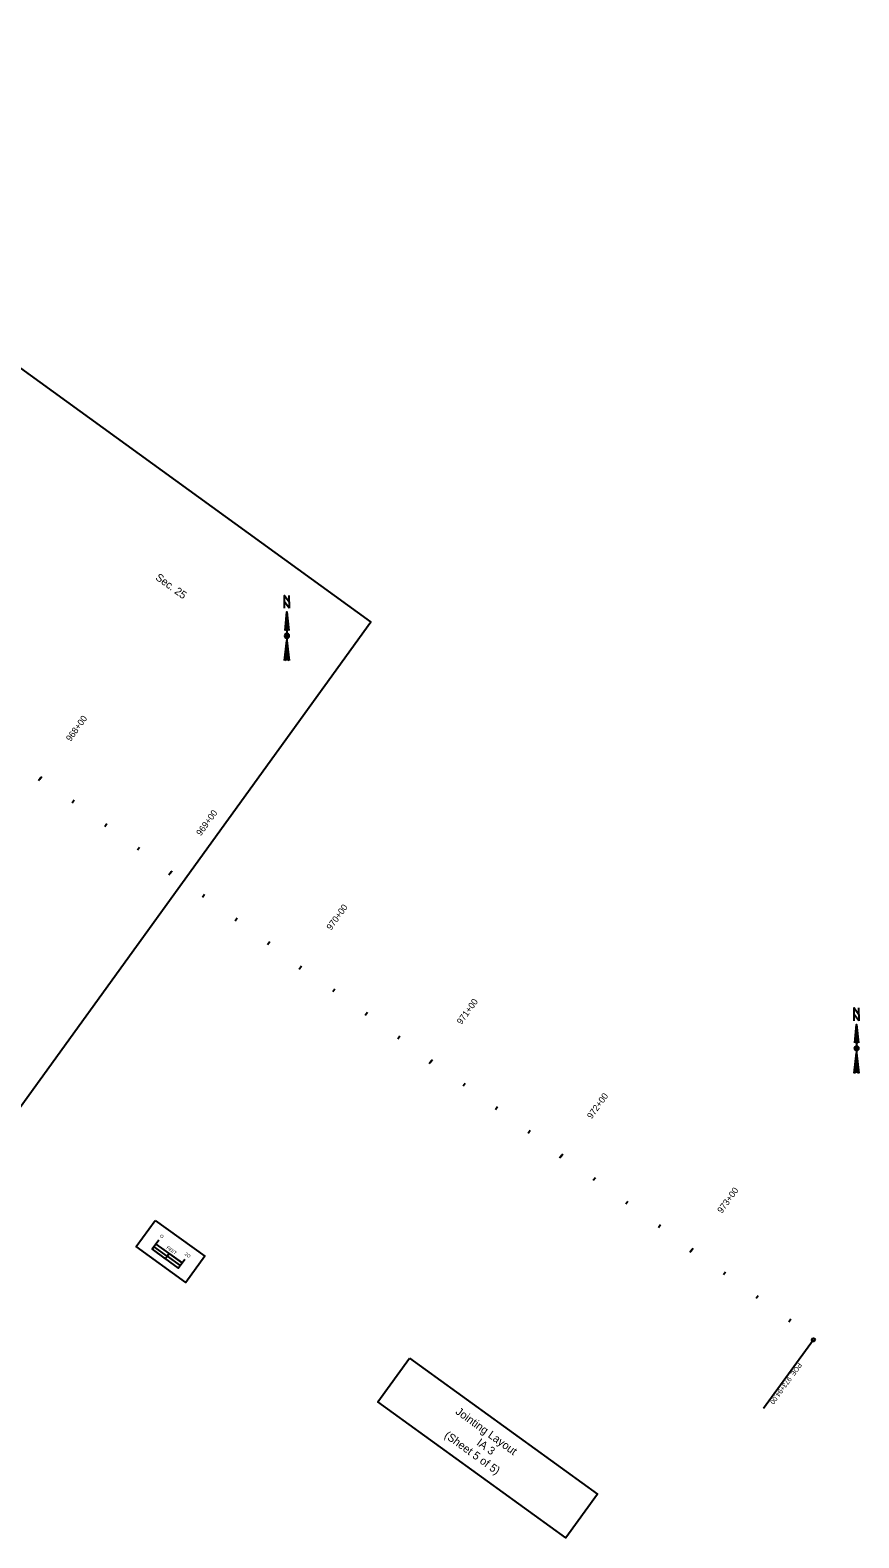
# Model space of a CAD drawing. Extents: x 14311466 to 14314811, y 8682098 to 8684603.
# Drawn here: x 14314296 to 14314811, y 8682098 to 8683035 of the extents above; entities that cross this region are included whole.
import ezdxf

# ---------------------------------------------------------------- set-up
doc = ezdxf.new("R2010")
doc.units = 0
for name, color, linetype in [('Cell', 7, 'Continuous'), ('Draft_8', 7, 'Continuous'), ('Draft_9', 7, 'Continuous'), ('NamedBoundary', 7, 'Continuous'), ('SheetText', 7, 'Continuous'), ('Text', 7, 'Continuous'), ('TextAlignment', 7, 'Continuous'), ('TextAlignmentLrg', 7, 'Continuous'), ('TextAlignmentSml', 7, 'Continuous')]:
    doc.layers.add(name, color=color, linetype=linetype)

msp = doc.modelspace()

# ---------------------------------------------------------------- linework, layer by layer
at = {"layer": 'Cell'}
for p, q in [((14314809.92, 8682417.14), (14314811.06, 8682405.73)), ((14314809.92, 8682417.14), (14314809.92, 8682387.48)), ((14314808.78, 8682405.73), (14314808.78, 8682405.73)), ((14314808.82, 8682405.84), (14314809.04, 8682406.07)), ((14314808.5, 8682386.9), (14314809.92, 8682399.45)), ((14314809.92, 8682400.88), (14314809.92, 8682400.88))]:
    msp.add_line(p, q, dxfattribs=at)
msp.add_lwpolyline([(14314811.35, 8682419.42), (14314808.5, 8682423.41), (14314808.5, 8682427.41), (14314811.35, 8682423.41)], close=True, dxfattribs=at)
for points in [[(14314808.5, 8682419.42), (14314808.5, 8682427.41), (14314811.35, 8682423.41), (14314811.35, 8682427.41)], [(14314808.78, 8682405.73), (14314809.92, 8682417.14), (14314809.92, 8682406.3)], [(14314809.92, 8682400.88), (14314809.92, 8682402.31), (14314808.5, 8682402.31)], [(14314811.35, 8682402.31), (14314809.92, 8682402.31), (14314809.92, 8682403.73)], [(14314809.92, 8682387.48), (14314809.92, 8682399.45), (14314811.35, 8682386.9)]]:
    msp.add_lwpolyline(points, dxfattribs=at)
for centre, radius, start, end in [((14314809.92, 8682404.87), 1.43, 90.02039, 143.12574), ((14314809.92, 8682404.88), 1.43, 36.84806, 90.02184), ((14314809.92, 8682402.31), 1.43, 90, 180), ((14314809.92, 8682402.31), 1.43, 180, 270), ((14314809.92, 8682402.31), 1.43, 0, 90), ((14314809.92, 8682402.31), 1.43, 270, 360), ((14314809.92, 8682385.41), 2.07, 89.98939, 133.61895), ((14314809.92, 8682385.41), 2.07, 46.40206, 90.00064)]:
    msp.add_arc(centre, radius, start, end, dxfattribs=at)
at = {"layer": 'Draft_8'}
for p, q in [((14314455.68, 8682673.47), (14314456.82, 8682662.06)), ((14314455.68, 8682673.47), (14314455.68, 8682643.81)), ((14314454.54, 8682662.06), (14314454.54, 8682662.06)), ((14314454.58, 8682662.17), (14314454.8, 8682662.4)), ((14314455.68, 8682657.21), (14314455.68, 8682657.21)), ((14314454.25, 8682643.24), (14314455.68, 8682655.79))]:
    msp.add_line(p, q, dxfattribs=at)
msp.add_lwpolyline([(14314457.11, 8682675.75), (14314454.25, 8682679.75), (14314454.25, 8682683.74), (14314457.11, 8682679.75)], close=True, dxfattribs=at)
for points in [[(14314454.25, 8682675.75), (14314454.25, 8682683.74), (14314457.11, 8682679.75), (14314457.11, 8682683.74)], [(14314454.54, 8682662.06), (14314455.68, 8682673.47), (14314455.68, 8682662.63)], [(14314455.68, 8682657.21), (14314455.68, 8682658.64), (14314454.25, 8682658.64)], [(14314457.11, 8682658.64), (14314455.68, 8682658.64), (14314455.68, 8682660.07)], [(14314455.68, 8682643.81), (14314455.68, 8682655.79), (14314457.11, 8682643.24)]]:
    msp.add_lwpolyline(points, dxfattribs=at)
for centre, radius, start, end in [((14314455.68, 8682658.64), 1.43, 90, 180), ((14314455.68, 8682658.64), 1.43, 180, 270), ((14314455.68, 8682661.21), 1.43, 90.02039, 143.12574), ((14314455.68, 8682661.21), 1.43, 36.84806, 90.02184), ((14314455.68, 8682658.64), 1.43, 0, 90), ((14314455.68, 8682658.64), 1.43, 270, 360), ((14314455.68, 8682641.74), 2.07, 89.98939, 133.61895), ((14314455.68, 8682641.74), 2.07, 46.40206, 90.00064)]:
    msp.add_arc(centre, radius, start, end, dxfattribs=at)
at = {"layer": 'Draft_9'}
msp.add_lwpolyline([(14314531.98, 8682209.86), (14314648.82, 8682125.27), (14314629.15, 8682098.1), (14314512.31, 8682182.7)], close=True, dxfattribs=at)
at = {"layer": 'NamedBoundary'}
msp.add_lwpolyline([(14314000.1, 8683035.05), (14313765.51, 8682711.06), (14314273.37, 8682343.35), (14314507.95, 8682667.35)], close=True, dxfattribs=at)
at = {"layer": 'SheetText'}
msp.add_line((14314380.03, 8682271.56), (14314382.38, 8682274.8), dxfattribs=at)
msp.add_line((14314380.03, 8682271.56), (14314382.38, 8682274.8), dxfattribs=at)
for points in [[(14314373.79, 8682295.34), (14314404.57, 8682273.05), (14314392.84, 8682256.85), (14314362.06, 8682279.14)], [(14314373.79, 8682295.34), (14314404.57, 8682273.05), (14314392.84, 8682256.85), (14314362.06, 8682279.14)], [(14314371.93, 8682277.42), (14314380.03, 8682271.56), (14314381.22, 8682273.19), (14314373.12, 8682279.05)], [(14314381.22, 8682273.19), (14314389.31, 8682267.32), (14314390.48, 8682268.93), (14314382.38, 8682274.8)]]:
    msp.add_lwpolyline(points, close=True, dxfattribs=at)
for points in [[(14314376.04, 8682283.09), (14314371.93, 8682277.42), (14314388.13, 8682265.69), (14314392.24, 8682271.36)], [(14314374.28, 8682280.66), (14314390.48, 8682268.93)]]:
    msp.add_lwpolyline(points, dxfattribs=at)
at = {"layer": 'TextAlignment'}
for p in [(14314783.09, 8682221.21), (14314752.13, 8682178.45)]:
    msp.add_line(p, (14314752.13, 8682178.45), dxfattribs=at)
msp.add_circle((14314783.09, 8682221.21), 1.07, dxfattribs=at)
at = {"layer": 'TextAlignmentLrg'}
for p, q in [((14314301.97, 8682569.57), (14314303.25, 8682571.34)), ((14314382.97, 8682510.92), (14314384.25, 8682512.69)), ((14314464.68, 8682453.27), (14314463.25, 8682451.28)), ((14314544.96, 8682393.63), (14314546.24, 8682395.4)), ((14314625.96, 8682334.98), (14314627.24, 8682336.75)), ((14314706.96, 8682276.34), (14314708.24, 8682278.11))]:
    msp.add_line(p, q, dxfattribs=at)
at = {"layer": 'TextAlignmentSml'}
for p, q in [((14314302.69, 8682570.56), (14314301.25, 8682568.58)), ((14314322.22, 8682554.91), (14314323.5, 8682556.67)), ((14314342.47, 8682540.24), (14314343.75, 8682542.01)), ((14314362.72, 8682525.58), (14314364, 8682527.35)), ((14314383.69, 8682511.91), (14314382.25, 8682509.93)), ((14314403.22, 8682496.26), (14314404.5, 8682498.03)), ((14314423.47, 8682481.6), (14314424.75, 8682483.37)), ((14314443.72, 8682466.94), (14314445, 8682468.71)), ((14314464.68, 8682453.27), (14314463.25, 8682451.28)), ((14314484.22, 8682437.61), (14314485.5, 8682439.38)), ((14314504.46, 8682422.95), (14314505.75, 8682424.72)), ((14314524.71, 8682408.29), (14314526, 8682410.06)), ((14314545.68, 8682394.62), (14314544.25, 8682392.64)), ((14314565.21, 8682378.97), (14314566.49, 8682380.74)), ((14314585.46, 8682364.31), (14314586.74, 8682366.08)), ((14314605.71, 8682349.65), (14314606.99, 8682351.41)), ((14314626.68, 8682335.97), (14314625.24, 8682333.99)), ((14314646.21, 8682320.32), (14314647.49, 8682322.09)), ((14314666.46, 8682305.66), (14314667.74, 8682307.43)), ((14314686.71, 8682291), (14314687.99, 8682292.77)), ((14314707.68, 8682277.33), (14314706.24, 8682275.35)), ((14314727.21, 8682261.68), (14314728.49, 8682263.45)), ((14314747.46, 8682247.01), (14314748.74, 8682248.78)), ((14314767.71, 8682232.35), (14314768.99, 8682234.12))]:
    msp.add_line(p, q, dxfattribs=at)

# ---------------------------------------------------------------- texts
at = {"layer": 'Draft_9'}
for s, p in [('Jointing Layout', (14314560.1, 8682175.59)), ('(Sheet 5 of 5)', (14314553.14, 8682160.87)), ('IA 3', (14314573.23, 8682156.2))]:
    msp.add_text(s, height=5, rotation=324.09397, dxfattribs=at).set_placement(p)
at = {"layer": 'SheetText'}
for s, p in [('O', (14314376.41, 8682285.29)), ('FEET', (14314380.58, 8682278.08)), ('2O', (14314391.9, 8682274.08))]:
    msp.add_text(s, height=2, rotation=324.09397, dxfattribs=at).set_placement(p)
at = {"layer": 'Text'}
msp.add_text('Sec. 25', height=4.8, rotation=324.0943, dxfattribs=at).set_placement((14314373.55, 8682693.98))
at = {"layer": 'TextAlignment'}
for s, p in [('973+94.00', (14314767.47, 8682198.5)), ('POE ', (14314773.78, 8682207.22))]:
    msp.add_text(s, height=3, rotation=234.09397, dxfattribs=at).set_placement(p)
at = {"layer": 'TextAlignmentLrg'}
msp.add_text('970+00', height=4.008, rotation=54.09397, dxfattribs=at).set_placement((14314483.18, 8682475.4))
at = {"layer": 'TextAlignmentSml'}
for s, p in [('968+00', (14314321.19, 8682592.69)), ('969+00', (14314402.18, 8682534.04)), ('970+00', (14314483.18, 8682475.4)), ('971+00', (14314564.18, 8682416.75)), ('972+00', (14314645.18, 8682358.11)), ('973+00', (14314726.18, 8682299.46))]:
    msp.add_text(s, height=4.008, rotation=54.09397, dxfattribs=at).set_placement(p)

doc.saveas('drawing.dxf')
